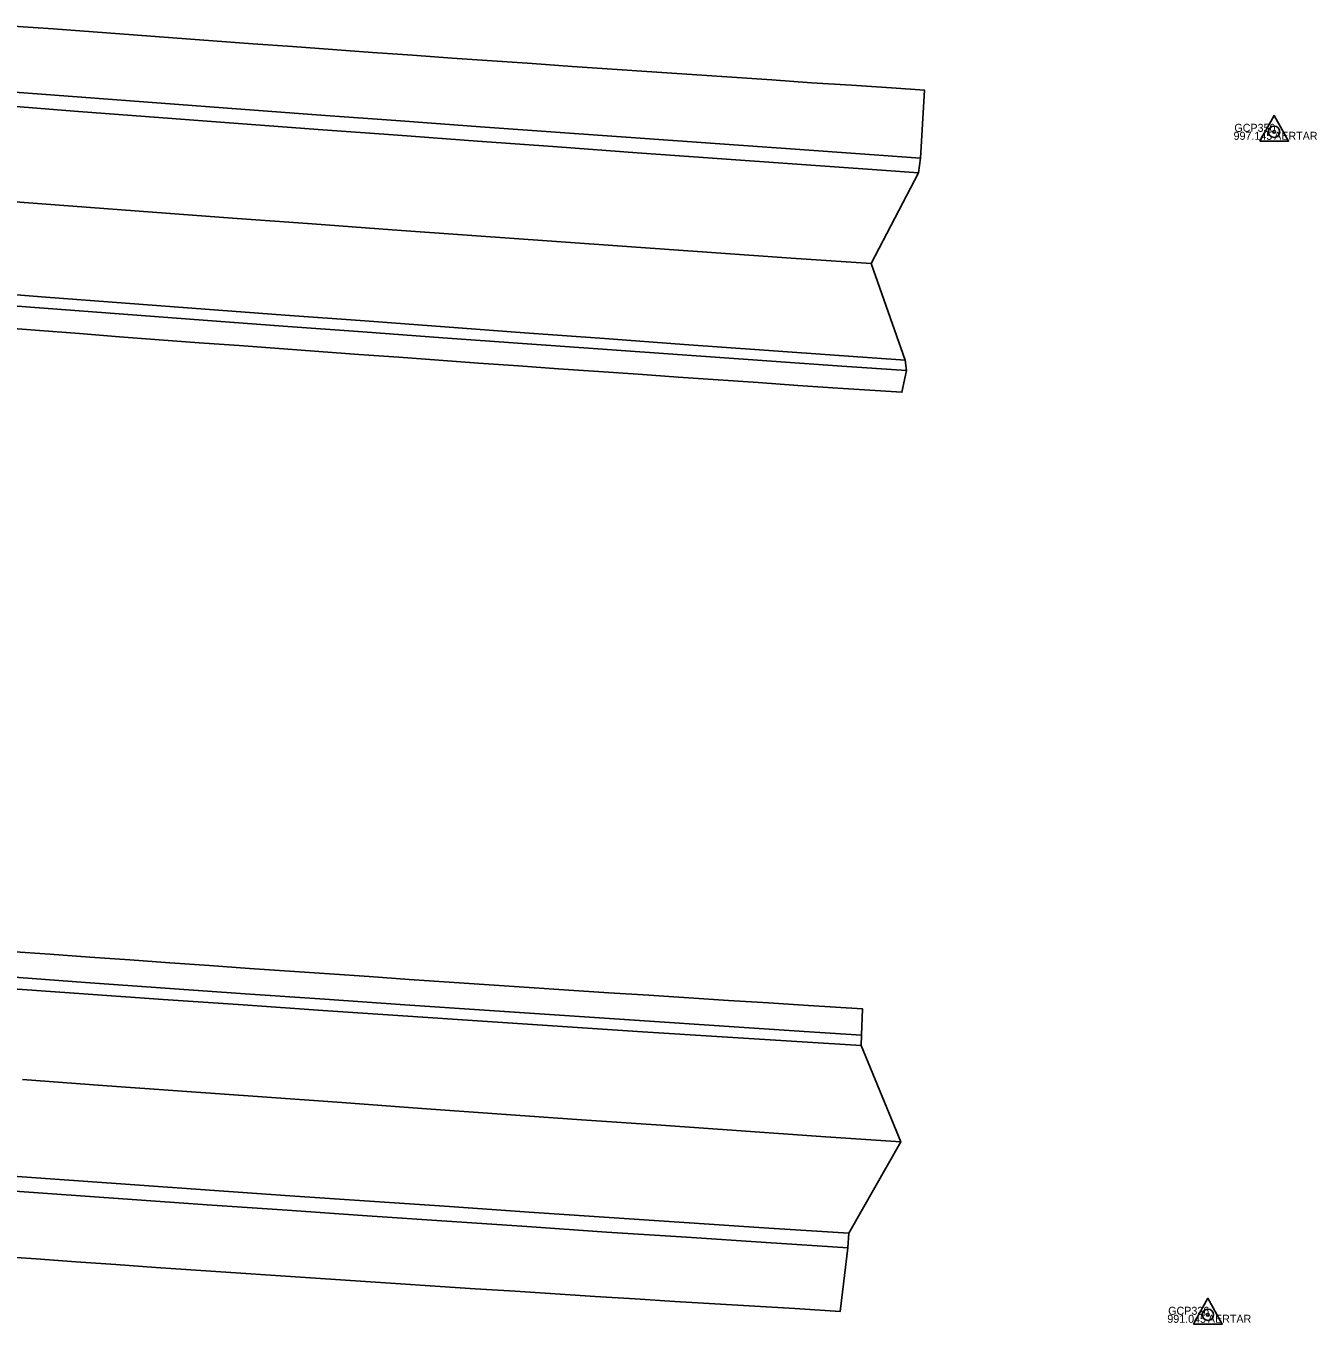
# Model space of a CAD drawing. Extents: x 2065431 to 2068157, y 709104 to 709719.
# Drawn here: x 2067995.7 to 2068157, y 709219.5 to 709381.7 of the extents above; entities that cross this region are included whole.
import ezdxf

# ---------------------------------------------------------------- set-up
doc = ezdxf.new("R2010")
doc.units = 0
for name, color, linetype in [('DT_X_Terrain_Boundary', 7, 'Continuous'), ('PM_X_Edge_Line', 7, 'Continuous'), ('PM_X_Lane_Line', 7, 'Continuous'), ('PV_X_EOP', 7, 'Continuous'), ('PV_X_Shoulder_Rumble_Strip', 7, 'Continuous'), ('SV_P_Aerial_Targets', 7, 'Continuous'), ('SV_X_Mon_Cells_Found', 7, 'Continuous'), ('SV_X_Text_Elevation', 7, 'Continuous'), ('SV_X_Text_Name', 7, 'Continuous')]:
    doc.layers.add(name, color=color, linetype=linetype)

msp = doc.modelspace()

# ---------------------------------------------------------------- linework, layer by layer
at = {"layer": 'DT_X_Terrain_Boundary'}
for points in [[(2067992.44, 709344), (2067997.43, 709343.62), (2068002.41, 709343.24), (2068007.4, 709342.86), (2068012.38, 709342.48), (2068017.37, 709342.11), (2068022.36, 709341.74), (2068027.34, 709341.37), (2068032.33, 709341.01), (2068037.32, 709340.64), (2068042.3, 709340.28), (2068047.29, 709339.92), (2068052.28, 709339.56), (2068057.26, 709339.21), (2068062.25, 709338.86), (2068067.24, 709338.5), (2068072.23, 709338.16), (2068077.22, 709337.81), (2068082.2, 709337.46), (2068087.19, 709337.12), (2068092.18, 709336.78), (2068097.17, 709336.44), (2068105.16, 709335.91), (2068105.76, 709338.63), (2068105.58, 709339.94), (2068101.31, 709351.98), (2068107.23, 709363.34), (2068107.48, 709365.18), (2068107.99, 709373.66), (2068103.87, 709373.93), (2068098.88, 709374.26), (2068093.89, 709374.59), (2068088.9, 709374.93), (2068083.91, 709375.26), (2068078.92, 709375.6), (2068073.93, 709375.94), (2068068.95, 709376.28), (2068063.96, 709376.63), (2068058.97, 709376.97), (2068053.98, 709377.32), (2068048.99, 709377.67), (2068044.01, 709378.03), (2068039.02, 709378.38), (2068034.03, 709378.74), (2068029.04, 709379.1), (2068024.06, 709379.46), (2068019.07, 709379.82), (2068014.08, 709380.19), (2068009.1, 709380.56), (2068004.11, 709380.93), (2067999.13, 709381.3), (2067994.14, 709381.67)], [(2067992, 709227.99), (2067996.99, 709227.64), (2068001.97, 709227.29), (2068006.96, 709226.94), (2068011.95, 709226.59), (2068016.94, 709226.25), (2068021.93, 709225.9), (2068026.91, 709225.57), (2068031.9, 709225.23), (2068036.89, 709224.9), (2068041.88, 709224.57), (2068046.87, 709224.24), (2068051.86, 709223.92), (2068056.85, 709223.6), (2068061.84, 709223.28), (2068066.83, 709222.97), (2068071.82, 709222.66), (2068076.81, 709222.35), (2068081.8, 709222.04), (2068086.79, 709221.74), (2068091.78, 709221.44), (2068097.46, 709221.1), (2068098.4, 709229.02), (2068098.52, 709230.85), (2068105.02, 709242.27), (2068100.06, 709254.29), (2068100.12, 709255.62), (2068100.24, 709258.9), (2068093.5, 709259.32), (2068088.51, 709259.63), (2068083.52, 709259.95), (2068078.53, 709260.27), (2068073.55, 709260.59), (2068068.56, 709260.91), (2068063.57, 709261.24), (2068058.58, 709261.57), (2068053.59, 709261.9), (2068048.6, 709262.24), (2068043.61, 709262.57), (2068038.62, 709262.91), (2068033.63, 709263.25), (2068028.65, 709263.6), (2068023.66, 709263.94), (2068018.67, 709264.29), (2068013.68, 709264.64), (2068008.69, 709265), (2068003.71, 709265.35), (2067998.72, 709265.71), (2067993.73, 709266.07)]]:
    msp.add_lwpolyline(points, dxfattribs=at)
at = {"layer": 'PM_X_Edge_Line'}
for points in [[(2067992.33, 709371.76), (2068002.3, 709371), (2068012.27, 709370.25), (2068022.25, 709369.5), (2068032.22, 709368.76), (2068042.19, 709368.02), (2068052.16, 709367.29), (2068062.14, 709366.56), (2068072.11, 709365.84), (2068082.09, 709365.12), (2068092.06, 709364.41), (2068102.04, 709363.71), (2068107.23, 709363.34)], [(2067988.22, 709348.57), (2067998.19, 709347.81), (2068008.16, 709347.05), (2068018.13, 709346.3), (2068028.1, 709345.56), (2068038.08, 709344.82), (2068048.05, 709344.08), (2068058.02, 709343.35), (2068068, 709342.62), (2068077.97, 709341.9), (2068087.95, 709341.19), (2068097.92, 709340.48), (2068105.58, 709339.94)], [(2067992.93, 709261.49), (2068002.9, 709260.77), (2068012.88, 709260.07), (2068022.85, 709259.37), (2068032.83, 709258.69), (2068042.81, 709258.01), (2068052.78, 709257.34), (2068062.76, 709256.68), (2068072.74, 709256.03), (2068082.72, 709255.39), (2068092.7, 709254.75), (2068100.06, 709254.29)], [(2067988.78, 709238.36), (2067998.76, 709237.65), (2068008.73, 709236.94), (2068018.71, 709236.24), (2068028.68, 709235.55), (2068038.66, 709234.86), (2068048.64, 709234.18), (2068058.61, 709233.5), (2068068.59, 709232.83), (2068078.57, 709232.16), (2068088.55, 709231.5), (2068098.52, 709230.85)]]:
    msp.add_lwpolyline(points, dxfattribs=at)
at = {"layer": 'PM_X_Lane_Line'}
for points in [[(2067991.6, 709359.92), (2068001.57, 709359.17), (2068011.54, 709358.42), (2068021.51, 709357.68), (2068031.49, 709356.94), (2068041.46, 709356.21), (2068051.44, 709355.49), (2068061.41, 709354.78), (2068071.38, 709354.07), (2068081.36, 709353.37), (2068091.34, 709352.67), (2068101.31, 709351.98)], [(2067995.3, 709250.05), (2068005.27, 709249.33), (2068015.25, 709248.6), (2068025.22, 709247.88), (2068035.2, 709247.17), (2068045.17, 709246.46), (2068055.14, 709245.75), (2068065.12, 709245.04), (2068075.1, 709244.34), (2068085.07, 709243.65), (2068095.05, 709242.96), (2068105.02, 709242.27)]]:
    msp.add_lwpolyline(points, dxfattribs=at)
at = {"layer": 'PV_X_EOP'}
for points in [[(2067994.14, 709381.67), (2067999.13, 709381.3), (2068004.11, 709380.93), (2068009.1, 709380.56), (2068014.08, 709380.19), (2068019.07, 709379.82), (2068024.06, 709379.46), (2068029.04, 709379.1), (2068034.03, 709378.74), (2068039.02, 709378.38), (2068044.01, 709378.03), (2068048.99, 709377.67), (2068053.98, 709377.32), (2068058.97, 709376.97), (2068063.96, 709376.63), (2068068.95, 709376.28), (2068073.93, 709375.94), (2068078.92, 709375.6), (2068083.91, 709375.26), (2068088.9, 709374.93), (2068093.89, 709374.59), (2068098.88, 709374.26), (2068103.87, 709373.93), (2068107.99, 709373.66)], [(2067992.44, 709344), (2067997.43, 709343.62), (2068002.41, 709343.24), (2068007.4, 709342.86), (2068012.38, 709342.48), (2068017.37, 709342.11), (2068022.36, 709341.74), (2068027.34, 709341.37), (2068032.33, 709341.01), (2068037.32, 709340.64), (2068042.3, 709340.28), (2068047.29, 709339.92), (2068052.28, 709339.56), (2068057.26, 709339.21), (2068062.25, 709338.86), (2068067.24, 709338.5), (2068072.23, 709338.16), (2068077.22, 709337.81), (2068082.2, 709337.46), (2068087.19, 709337.12), (2068092.18, 709336.78), (2068097.17, 709336.44), (2068105.16, 709335.91)], [(2067993.73, 709266.07), (2067998.72, 709265.71), (2068003.71, 709265.35), (2068008.69, 709265), (2068013.68, 709264.64), (2068018.67, 709264.29), (2068023.66, 709263.94), (2068028.65, 709263.6), (2068033.63, 709263.25), (2068038.62, 709262.91), (2068043.61, 709262.57), (2068048.6, 709262.24), (2068053.59, 709261.9), (2068058.58, 709261.57), (2068063.57, 709261.24), (2068068.56, 709260.91), (2068073.55, 709260.59), (2068078.53, 709260.27), (2068083.52, 709259.95), (2068088.51, 709259.63), (2068093.5, 709259.32), (2068100.24, 709258.9)], [(2067992, 709227.99), (2067996.99, 709227.64), (2068001.97, 709227.29), (2068006.96, 709226.94), (2068011.95, 709226.59), (2068016.94, 709226.25), (2068021.93, 709225.9), (2068026.91, 709225.57), (2068031.9, 709225.23), (2068036.89, 709224.9), (2068041.88, 709224.57), (2068046.87, 709224.24), (2068051.86, 709223.92), (2068056.85, 709223.6), (2068061.84, 709223.28), (2068066.83, 709222.97), (2068071.82, 709222.66), (2068076.81, 709222.35), (2068081.8, 709222.04), (2068086.79, 709221.74), (2068091.78, 709221.44), (2068097.46, 709221.1)]]:
    msp.add_lwpolyline(points, dxfattribs=at)
at = {"layer": 'PV_X_Shoulder_Rumble_Strip'}
for points in [[(2067992.67, 709373.54), (2068002.65, 709372.78), (2068012.62, 709372.03), (2068022.59, 709371.29), (2068032.56, 709370.55), (2068042.53, 709369.82), (2068052.51, 709369.09), (2068062.48, 709368.37), (2068072.46, 709367.65), (2068082.43, 709366.94), (2068092.41, 709366.23), (2068107.48, 709365.18)], [(2067987.96, 709347.18), (2067997.94, 709346.42), (2068007.91, 709345.67), (2068017.88, 709344.93), (2068027.85, 709344.19), (2068037.83, 709343.45), (2068047.8, 709342.73), (2068057.77, 709342.01), (2068067.75, 709341.29), (2068077.72, 709340.58), (2068087.7, 709339.88), (2068097.67, 709339.19), (2068105.76, 709338.63)], [(2067993.18, 709262.91), (2068003.15, 709262.19), (2068013.13, 709261.48), (2068023.1, 709260.78), (2068033.08, 709260.09), (2068043.05, 709259.4), (2068053.03, 709258.72), (2068063.01, 709258.05), (2068072.99, 709257.39), (2068082.96, 709256.73), (2068092.94, 709256.08), (2068100.12, 709255.62)], [(2067988.46, 709236.54), (2067998.43, 709235.83), (2068008.41, 709235.12), (2068018.38, 709234.42), (2068028.36, 709233.73), (2068038.34, 709233.04), (2068048.31, 709232.36), (2068058.29, 709231.68), (2068068.27, 709231.01), (2068078.25, 709230.35), (2068088.22, 709229.69), (2068098.4, 709229.02)]]:
    msp.add_lwpolyline(points, dxfattribs=at)
at = {"layer": 'SV_P_Aerial_Targets'}
for points in [[(2068149.88, 709367.29), (2068153.48, 709367.29), (2068151.68, 709370.51)], [(2068141.6, 709219.51), (2068145.2, 709219.51), (2068143.4, 709222.73)]]:
    msp.add_lwpolyline(points, close=True, dxfattribs=at)
for centre, radius in [((2068151.68, 709368.45), 0.7), ((2068151.68, 709368.45), 0.16), ((2068143.4, 709220.67), 0.7), ((2068143.4, 709220.67), 0.16)]:
    msp.add_circle(centre, radius, dxfattribs=at)

# ---------------------------------------------------------------- texts
at = {"layer": 'SV_X_Mon_Cells_Found'}
for s, p in [('GCP350', (2068146.71, 709368.45)), ('GCP336', (2068138.44, 709220.67))]:
    msp.add_text(s, height=1, dxfattribs=at).set_placement(p)
at = {"layer": 'SV_X_Text_Elevation'}
for p in [(2068151.68, 709367.45), (2068143.4, 709219.67)]:
    msp.add_text('AERTAR', height=1, dxfattribs=at).set_placement(p)
at = {"layer": 'SV_X_Text_Name'}
for s, p in [('997.145', (2068146.61, 709367.45)), ('991.045', (2068138.33, 709219.67))]:
    msp.add_text(s, height=1, dxfattribs=at).set_placement(p)

doc.saveas('drawing.dxf')
